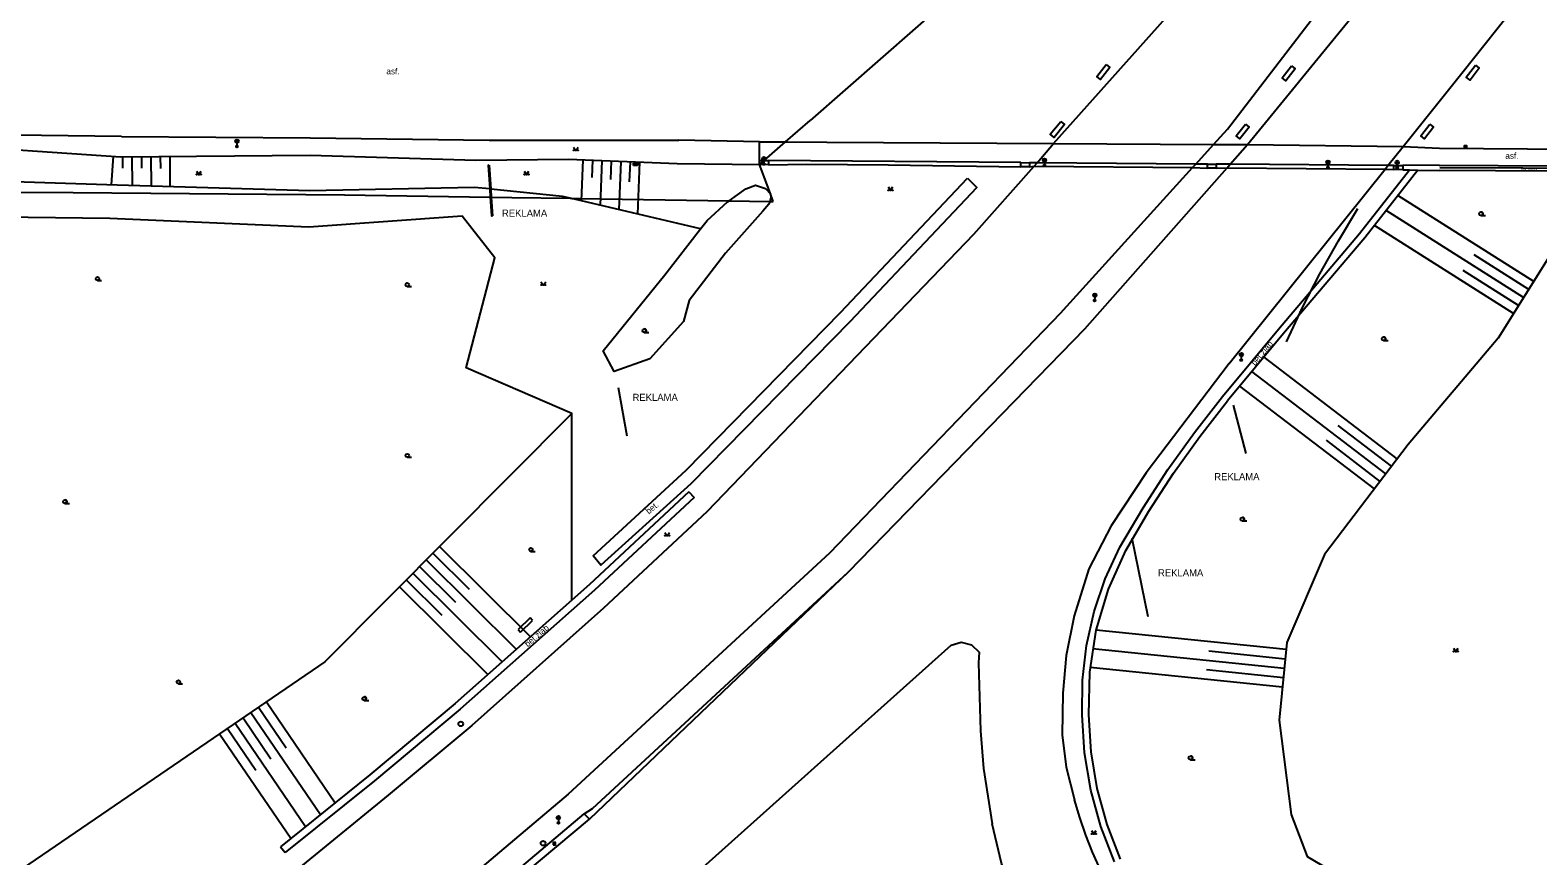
# Model space of a CAD drawing. Extents: x -602419 to -601554, y -1162937 to -1162362.
# Drawn here: x -601894 to -601734.4, y -1162806.1 to -1162718.7 of the extents above; entities that cross this region are included whole.
import ezdxf

# ---------------------------------------------------------------- set-up
doc = ezdxf.new("R2010")
doc.units = 0
doc.layers.add('Podklad', color=7, linetype='Continuous')

msp = doc.modelspace()

# ---------------------------------------------------------------- linework, layer by layer
at = {"layer": 'Podklad'}
for p, q in [((-601872.2825, -1162730.6), (-601872.0175, -1162730.335)), ((-601872.2825, -1162730.335), (-601872.0175, -1162730.6)), ((-601872.15, -1162730.655), (-601872.15, -1162731.03)), ((-601742.225, -1162731.1), (-601741.975, -1162731.1)), ((-601816.5025, -1162732.46), (-601816.2375, -1162732.195)), ((-601816.5025, -1162732.195), (-601816.2375, -1162732.46)), ((-601816.37, -1162732.515), (-601816.37, -1162732.89)), ((-601786.8025, -1162732.61), (-601786.5375, -1162732.345)), ((-601786.8025, -1162732.345), (-601786.5375, -1162732.61)), ((-601786.67, -1162732.665), (-601786.67, -1162733.04)), ((-601756.7925, -1162732.83), (-601756.5275, -1162732.565)), ((-601756.7925, -1162732.565), (-601756.5275, -1162732.83)), ((-601756.66, -1162732.885), (-601756.66, -1162733.26)), ((-601749.4625, -1162732.85), (-601749.1975, -1162732.585)), ((-601749.4625, -1162732.585), (-601749.1975, -1162732.85)), ((-601749.33, -1162732.905), (-601749.33, -1162733.28)), ((-601740.47, -1162738.3375), (-601739.97, -1162738.3375)), ((-601886.92, -1162745.2075), (-601886.4825, -1162745.2075)), ((-601854.12, -1162745.8475), (-601853.6825, -1162745.8475)), ((-601781.4774, -1162746.8856), (-601781.2033, -1162746.63)), ((-601781.4682, -1162746.6208), (-601781.2126, -1162746.8949)), ((-601781.3469, -1162746.9452), (-601781.36, -1162747.32)), ((-601829.05, -1162750.7075), (-601828.55, -1162750.7075)), ((-601750.78, -1162751.5575), (-601750.28, -1162751.5575)), ((-601765.9674, -1162753.1856), (-601765.6933, -1162752.93)), ((-601765.9582, -1162752.9208), (-601765.7026, -1162753.1949)), ((-601765.8369, -1162753.2452), (-601765.85, -1162753.62)), ((-601854.12, -1162763.9075), (-601853.6825, -1162763.9075)), ((-601890.38, -1162768.7875), (-601889.88, -1162768.7875)), ((-601765.74, -1162770.6375), (-601765.24, -1162770.6375)), ((-601841.03, -1162773.8675), (-601840.5925, -1162773.8675)), ((-601878.35, -1162787.8675), (-601877.9125, -1162787.8675)), ((-601858.7, -1162789.6175), (-601858.2, -1162789.6175)), ((-601771.22, -1162795.8875), (-601770.72, -1162795.8875)), ((-601838.2625, -1162802.15), (-601837.9975, -1162801.885)), ((-601838.2625, -1162801.885), (-601837.9975, -1162802.15)), ((-601838.13, -1162802.205), (-601838.13, -1162802.58)), ((-601838.685, -1162804.77), (-601838.435, -1162804.77))]:
    msp.add_line(p, q, dxfattribs=at)
for points in [[(-601793.98, -1162712.96), (-601794.4894, -1162713.4059), (-601796.6372, -1162715.2857), (-601811.4818, -1162728.2775)], [(-601785.71, -1162730.7199), (-601773.83, -1162717.43), (-601771.84, -1162715.44)], [(-601768.78, -1162730.81), (-601767.31, -1162729.19), (-601756.8, -1162715.56)], [(-601765.17, -1162730.83), (-601754.24, -1162717.46), (-601752.54, -1162715.58)], [(-601742.35, -1162723.1), (-601736.4699, -1162715.71)], [(-601780.14, -1162722.37), (-601779.75, -1162722.68), (-601780.75, -1162723.94), (-601781.14, -1162723.63), (-601780.14, -1162722.37)], [(-601760.51, -1162722.51), (-601760.12, -1162722.82), (-601761.12, -1162724.09), (-601761.51, -1162723.77), (-601760.51, -1162722.51)], [(-601741.04, -1162722.45), (-601740.64, -1162722.76), (-601741.62, -1162724.02), (-601742.02, -1162723.7199), (-601741.04, -1162722.45)], [(-601748.71, -1162731.03), (-601742.35, -1162723.1)], [(-601816.82, -1162732.95), (-601816.3348, -1162732.5252), (-601814.0843, -1162730.5554), (-601811.4817, -1162728.2776)], [(-601784.95, -1162728.39), (-601784.56, -1162728.7), (-601785.65, -1162730.07), (-601786.05, -1162729.75), (-601784.95, -1162728.39)], [(-601765.4, -1162728.67), (-601765, -1162728.98), (-601765.99, -1162730.2199), (-601766.38, -1162729.9099), (-601765.4, -1162728.67)], [(-601745.88, -1162728.68), (-601745.48, -1162728.98), (-601746.43, -1162730.21), (-601746.83, -1162729.9), (-601745.88, -1162728.68)], [(-601884.36, -1162729.99), (-601904.12, -1162729.75), (-601924.49, -1162729.7), (-601937.13, -1162729.6599)], [(-601884.36, -1162729.99), (-601864.41, -1162730.11), (-601845.45, -1162730.36)], [(-601845.45, -1162730.36), (-601825.39, -1162730.38)], [(-601816.83, -1162730.54), (-601825.39, -1162730.38)], [(-601816.83, -1162730.54), (-601814.0843, -1162730.5554), (-601809.7199, -1162730.58)], [(-601816.82, -1162732.52), (-601816.83, -1162730.54)], [(-601947.91, -1162731.01), (-601924.66, -1162730.88), (-601904.2, -1162730.78), (-601884.43, -1162732.12), (-601864.39, -1162731.97), (-601846.88, -1162732.47), (-601837.05, -1162732.39)], [(-601885.27, -1162732.06), (-601885.47, -1162735.1)], [(-601884.27, -1162732.12), (-601884.26, -1162733.33)], [(-601883.27, -1162732.11), (-601883.25, -1162735.17)], [(-601882.27, -1162732.1), (-601882.26, -1162733.34)], [(-601881.27, -1162732.1), (-601881.25, -1162735.23)], [(-601880.27, -1162732.09), (-601880.26, -1162733.36)], [(-601879.27, -1162732.08), (-601879.25, -1162735.29)], [(-601836.53, -1162731.095), (-601836.28, -1162731.47), (-601836.03, -1162731.095)], [(-601809.7199, -1162730.58), (-601785.71, -1162730.7199)], [(-601787.76, -1162733.12), (-601787.4491, -1162732.7561), (-601785.71, -1162730.7199)], [(-601785.71, -1162730.7199), (-601768.78, -1162730.81)], [(-601770.99, -1162733.25), (-601770.6641, -1162732.8901), (-601768.78, -1162730.81)], [(-601768.78, -1162730.81), (-601765.17, -1162730.83)], [(-601767.34, -1162733.28), (-601767.013, -1162732.9109), (-601765.17, -1162730.83)], [(-601765.17, -1162730.83), (-601748.71, -1162731.03)], [(-601750.62, -1162733.42), (-601750.32, -1162733.0447), (-601748.71, -1162731.03)], [(-601748.71, -1162731.03), (-601744.87, -1162731.2), (-601726.21, -1162731.37)], [(-601876.45, -1162733.645), (-601876.2, -1162734.02), (-601875.95, -1162733.645)], [(-601845.46, -1162733.01), (-601845.57, -1162733.03), (-601845.4, -1162735.53)], [(-601845.46, -1162733.01), (-601845.29, -1162735.54)], [(-601841.74, -1162733.645), (-601841.49, -1162734.02), (-601841.24, -1162733.645)], [(-601837.05, -1162732.39), (-601825.54, -1162732.85)], [(-601835.53, -1162732.45), (-601835.7, -1162736.8)], [(-601834.53, -1162732.49), (-601834.6, -1162734.31)], [(-601833.53, -1162732.53), (-601833.72, -1162737.26)], [(-601832.53, -1162732.57), (-601832.61, -1162734.54)], [(-601831.53, -1162732.61), (-601831.74, -1162737.73)], [(-601830.53, -1162732.65), (-601830.62, -1162734.77)], [(-601830.18, -1162733.03), (-601830.17, -1162732.81)], [(-601829.76, -1162733.03), (-601830.18, -1162733.03)], [(-601830.17, -1162732.81), (-601829.75, -1162732.81)], [(-601829.75, -1162732.81), (-601829.76, -1162733.03)], [(-601829.53, -1162732.69), (-601829.75, -1162738.19)], [(-601825.54, -1162732.85), (-601816.82, -1162732.95)], [(-601816.82, -1162732.95), (-601816.82, -1162732.52)], [(-601816.82, -1162732.52), (-601816.3348, -1162732.5252), (-601815.89, -1162732.53), (-601815.89, -1162732.71), (-601815.89, -1162732.96)], [(-601815.38, -1162736.85), (-601815.6727, -1162736.0572), (-601815.7178, -1162735.9351), (-601816.82, -1162732.95)], [(-601815.89, -1162732.96), (-601816.82, -1162732.95)], [(-601789.17, -1162732.74), (-601815.89, -1162732.53)], [(-601815.89, -1162732.96), (-601811.83, -1162732.92)], [(-601811.83, -1162732.92), (-601803.2199, -1162732.99), (-601789.17, -1162733.17)], [(-601794.14, -1162740.3), (-601787.76, -1162733.12)], [(-601789.17, -1162732.92), (-601789.17, -1162732.74), (-601788.24, -1162732.75), (-601788.24, -1162732.93), (-601788.24, -1162733.18)], [(-601789.17, -1162733.17), (-601789.17, -1162732.92)], [(-601788.24, -1162733.18), (-601789.17, -1162733.17)], [(-601769.42, -1162732.9), (-601770.6641, -1162732.8901), (-601787.4491, -1162732.7561), (-601788.24, -1162732.75)], [(-601788.24, -1162733.18), (-601787.76, -1162733.12)], [(-601787.76, -1162733.12), (-601770.99, -1162733.25)], [(-601784.98, -1162748.68), (-601770.99, -1162733.25)], [(-601782.4, -1162750.32), (-601767.34, -1162733.28)], [(-601770.99, -1162733.25), (-601769.42, -1162733.33)], [(-601769.42, -1162733.08), (-601769.42, -1162732.9), (-601768.5, -1162732.9), (-601768.5, -1162733.08), (-601768.5, -1162733.33)], [(-601769.42, -1162733.33), (-601769.42, -1162733.08)], [(-601768.5, -1162733.33), (-601769.42, -1162733.33)], [(-601749.68, -1162733.05), (-601750.32, -1162733.0447), (-601767.013, -1162732.9109), (-601768.5, -1162732.9)], [(-601768.5, -1162733.33), (-601767.34, -1162733.28)], [(-601767.82, -1162757.49), (-601761.89, -1162750.36), (-601753.31, -1162740.25), (-601748.03, -1162733.51)], [(-601767.34, -1162733.28), (-601750.62, -1162733.42)], [(-601747.14, -1162733.53), (-601752.77, -1162740.69), (-601761.35, -1162750.82), (-601767.28, -1162757.93)], [(-601767.11, -1162754), (-601750.62, -1162733.42)], [(-601726.17, -1162733.7), (-601732.68, -1162738.79), (-601733.02, -1162742.36), (-601738.66, -1162751.3), (-601748.18, -1162762.56), (-601757.04, -1162774.19), (-601761, -1162783.51), (-601761.84, -1162791.71), (-601760.56, -1162801.67), (-601758.87, -1162806.14), (-601753, -1162809.59)], [(-601750.62, -1162733.42), (-601749.68, -1162733.48)], [(-601749.68, -1162733.23), (-601749.68, -1162733.05), (-601748.74, -1162733.06), (-601748.74, -1162733.24), (-601748.74, -1162733.49)], [(-601749.68, -1162733.48), (-601749.68, -1162733.23)], [(-601748.74, -1162733.49), (-601749.68, -1162733.48)], [(-601744.89, -1162733), (-601748.74, -1162733.06)], [(-601748.74, -1162733.49), (-601748.03, -1162733.51), (-601747.14, -1162733.53), (-601744.86, -1162733.58)], [(-601744.89, -1162733), (-601726.19, -1162733.13)], [(-601726.19, -1162733.13), (-601726.17, -1162733.7), (-601726.26, -1162733.7), (-601727.04, -1162733.69), (-601744.86, -1162733.58)], [(-601727.23, -1162733.38), (-601744.83, -1162733.28)], [(-601845.4, -1162735.53), (-601847.05, -1162735.36), (-601864.45, -1162735.74), (-601884.84, -1162735.12), (-601903.48, -1162734.51), (-601924.34, -1162734.49), (-601947.95, -1162734.55)], [(-601794.83, -1162734.39), (-601793.82, -1162735.38), (-601807.27, -1162749.57), (-601820.33, -1162762.86), (-601824.12, -1162766.71), (-601833.64, -1162775.33), (-601834.46, -1162774.33), (-601824.6, -1162765.26), (-601821.24, -1162761.86), (-601808.28, -1162748.59), (-601794.83, -1162734.39)], [(-601826.86, -1162744.62), (-601823.08, -1162739.76), (-601822.38, -1162738.86), (-601820.21, -1162736.89), (-601820.05, -1162736.78), (-601818.29, -1162735.53), (-601817.25, -1162735.13), (-601816.2, -1162735.49), (-601815.67, -1162736.06), (-601815.64, -1162736.45), (-601815.76, -1162736.84), (-601815.84, -1162737.13), (-601816.49, -1162737.86), (-601820.45, -1162742.31), (-601824.3, -1162747.32), (-601824.87, -1162749.54)], [(-601803.23, -1162735.315), (-601802.98, -1162735.69), (-601802.73, -1162735.315)], [(-601978.25, -1162735.53), (-601954.18, -1162735.627), (-601889.49, -1162735.89), (-601860.77, -1162736.15), (-601845.34, -1162736.39)], [(-601845.29, -1162735.54), (-601845.4, -1162735.53)], [(-601845.4, -1162735.53), (-601845.34, -1162736.39)], [(-601845.34, -1162736.39), (-601845.24, -1162736.39)], [(-601845.34, -1162736.39), (-601845.2, -1162738.38), (-601845.11, -1162738.37)], [(-601845.29, -1162735.54), (-601845.24, -1162736.39)], [(-601823.08, -1162739.76), (-601836.8835, -1162736.5171), (-601837.68, -1162736.33), (-601845.29, -1162735.54)], [(-601845.24, -1162736.39), (-601843.06, -1162736.42), (-601836.8835, -1162736.5171), (-601836.7, -1162736.52), (-601835.88, -1162736.53), (-601820.0506, -1162736.7771), (-601815.7559, -1162736.8441), (-601815.38, -1162736.85)], [(-601845.24, -1162736.39), (-601845.11, -1162738.37)], [(-601734.88, -1162745.31), (-601749.27, -1162736.23)], [(-601836.71, -1162779), (-601836.71, -1162759.26), (-601847.88, -1162754.46), (-601844.85, -1162742.8), (-601848.33, -1162738.42), (-601864.53, -1162739.57), (-601885.6, -1162738.66), (-601902.92, -1162738.45), (-601924.69, -1162739.17), (-601946.88, -1162737.91), (-601963.34, -1162737.04), (-601979.03, -1162737.55), (-601989.84, -1162739.24)], [(-601761.06, -1162751.69), (-601759.35, -1162748.07), (-601757.51, -1162744.51), (-601755.56, -1162741.02), (-601753.49, -1162737.59)], [(-601735.95, -1162747), (-601750.51, -1162737.81)], [(-601737.01, -1162748.69), (-601751.75, -1162739.39)], [(-601794.14, -1162740.3), (-601822.43, -1162769.67)], [(-601735.41, -1162746.15), (-601741.2, -1162742.5)], [(-601824.87, -1162749.54), (-601828.46, -1162753.49), (-601832.23, -1162754.82), (-601833.4, -1162752.64), (-601826.86, -1162744.62)], [(-601736.48, -1162747.84), (-601742.34, -1162744.15)], [(-601839.97, -1162745.335), (-601839.72, -1162745.71), (-601839.47, -1162745.335)], [(-601784.98, -1162748.68), (-601809.42, -1162774.04), (-601837.09, -1162799.55), (-601848.91, -1162809.52), (-601861.6, -1162819.71), (-601867.21, -1162824.05), (-601886.81, -1162838.4), (-601901.63, -1162848.6), (-601920.894, -1162861.0918), (-601922.609, -1162862.2039), (-601926.89, -1162864.98), (-601937.36, -1162871.29)], [(-601782.4, -1162750.32), (-601807.45, -1162776.07), (-601834.85, -1162802.17)], [(-601767.11, -1162754), (-601775.91, -1162765.56), (-601779.61, -1162771.16), (-601781.99, -1162775.7), (-601783.53, -1162780.67), (-601784.37, -1162784.86), (-601784.72, -1162788.85), (-601784.79, -1162793.26), (-601784.37, -1162796.68), (-601783.49, -1162800.14)], [(-601749.32, -1162764.06), (-601763.43, -1162753.31)], [(-601750.53, -1162765.65), (-601764.71, -1162754.85)], [(-601830.84, -1162761.69), (-601831.76, -1162756.57)], [(-601778.68, -1162773.41), (-601776.23, -1162769.26), (-601773.6, -1162765.21), (-601770.79, -1162761.29), (-601767.82, -1162757.49)], [(-601751.75, -1162767.24), (-601765.99, -1162756.39)], [(-601836.71, -1162759.26), (-601862.84, -1162785.54), (-601906.04, -1162815.02)], [(-601778.06, -1162773.75), (-601775.63, -1162769.62), (-601773.02, -1162765.6), (-601770.23, -1162761.71), (-601767.28, -1162757.93)], [(-601766.68, -1162758.39), (-601765.34, -1162763.51)], [(-601749.93, -1162764.85), (-601755.59, -1162760.54)], [(-601751.14, -1162766.45), (-601756.83, -1162762.11)], [(-601824.31, -1162767.57), (-601834.85, -1162777.35), (-601836.71, -1162779), (-601849.04, -1162789.93), (-601858.08, -1162797.5), (-601867.55, -1162805.09)], [(-601823.77, -1162768.15), (-601834.31, -1162777.95), (-601848.52, -1162790.53), (-601857.58, -1162798.12), (-601867.05, -1162805.71)], [(-601824.31, -1162767.57), (-601823.77, -1162768.15)], [(-601822.43, -1162769.67), (-601833.34, -1162779.85), (-601847.28, -1162792.26), (-601856.16, -1162799.64), (-601865.61, -1162807.35)], [(-601826.87, -1162771.845), (-601826.62, -1162772.22), (-601826.37, -1162771.845)], [(-601850.7, -1162773.33), (-601841.09, -1162782.88)], [(-601782.68, -1162791.15), (-601782.65, -1162787.47), (-601782.22, -1162783.82), (-601781.41, -1162780.23), (-601780.23, -1162776.75), (-601778.68, -1162773.41)], [(-601777.42, -1162772.46), (-601775.74, -1162780.75)], [(-601852.11, -1162774.75), (-601842.59, -1162784.21)], [(-601851.41, -1162774.04), (-601847.58, -1162777.84)], [(-601781.98, -1162791.13), (-601781.88, -1162786.63), (-601781.19, -1162782.18), (-601779.91, -1162777.86), (-601778.06, -1162773.75)], [(-601853.52, -1162776.17), (-601844.09, -1162785.54)], [(-601852.82, -1162775.46), (-601849.03, -1162779.23)], [(-601835.39, -1162801.6), (-601834.51, -1162801.05), (-601807.45, -1162776.07)], [(-601854.93, -1162777.59), (-601845.59, -1162786.87)], [(-601854.23, -1162776.88), (-601850.47, -1162780.61)], [(-601841.13, -1162780.88), (-601842.4, -1162782.12)], [(-601842.12, -1162782.41), (-601840.85, -1162781.17)], [(-601840.85, -1162781.17), (-601841.13, -1162780.88)], [(-601842.4, -1162782.12), (-601842.12, -1162782.41)], [(-601761.08, -1162784.24), (-601781.19, -1162782.18)], [(-601826.5, -1162810.58), (-601796.55, -1162783.76)], [(-601796.55, -1162783.76), (-601795.48, -1162783.45), (-601794.39, -1162783.73), (-601793.6, -1162784.52), (-601793.67, -1162785.64)], [(-601761.28, -1162786.23), (-601781.57, -1162784.15)], [(-601761.18, -1162785.24), (-601769.26, -1162784.41)], [(-601743.38, -1162784.095), (-601743.13, -1162784.47), (-601742.88, -1162784.095)], [(-601793.67, -1162785.64), (-601793.46, -1162792.84), (-601793.11, -1162796.82), (-601792.2, -1162802.67)], [(-601761.48, -1162788.22), (-601781.84, -1162786.14)], [(-601761.38, -1162787.23), (-601769.52, -1162786.39)], [(-601870.69, -1162790.9), (-601863.32, -1162801.7)], [(-601869.86, -1162790.33), (-601866.93, -1162794.63)], [(-601869.04, -1162789.77), (-601861.75, -1162800.44)], [(-601779.25, -1162806.7), (-601780.7, -1162802.96), (-601781.77, -1162799.1), (-601782.43, -1162795.15), (-601782.68, -1162791.15)], [(-601778.61, -1162806.4), (-601780.04, -1162802.73), (-601781.09, -1162798.94), (-601781.73, -1162795.06), (-601781.98, -1162791.13)], [(-601873.17, -1162792.59), (-601870.17, -1162796.98)], [(-601872.34, -1162792.02), (-601864.88, -1162802.95)], [(-601871.51, -1162791.46), (-601868.55, -1162795.8)], [(-601873.99, -1162793.15), (-601866.45, -1162804.2)], [(-601780.77, -1162807.45), (-601781.58, -1162805.67), (-601782.3, -1162803.86), (-601782.94, -1162802.01), (-601783.49, -1162800.14)], [(-601859.94, -1162821.88), (-601847.21, -1162811.6), (-601835.39, -1162801.6)], [(-601859.51, -1162822.54), (-601856.32, -1162819.91), (-601846.71, -1162812.11), (-601834.85, -1162802.17)], [(-601835.39, -1162801.6), (-601834.85, -1162802.17)], [(-601785.69, -1162818.33), (-601787.95, -1162814.7), (-601789.8, -1162810.85), (-601791.22, -1162806.83), (-601792.2, -1162802.67)], [(-601781.69, -1162803.385), (-601781.44, -1162803.76), (-601781.19, -1162803.385)], [(-601867.55, -1162805.09), (-601867.05, -1162805.71)]]:
    msp.add_lwpolyline(points, dxfattribs=at)
for points in [[(-601742.225, -1162731.225), (-601741.975, -1162731.225), (-601741.975, -1162730.975), (-601742.225, -1162730.975)], [(-601838.685, -1162804.895), (-601838.435, -1162804.895), (-601838.435, -1162804.645), (-601838.685, -1162804.645)]]:
    msp.add_lwpolyline(points, close=True, dxfattribs=at)
for centre, radius in [((-601872.15, -1162730.4675), 0.1875), ((-601872.15, -1162731.03), 0.1), ((-601872.15, -1162731.03), 0.0723), ((-601872.15, -1162731.03), 0.0438), ((-601836.5051, -1162731.4449), 0.025), ((-601836.0554, -1162731.4449), 0.025), ((-601816.37, -1162732.3275), 0.1875), ((-601816.37, -1162732.89), 0.1), ((-601816.37, -1162732.89), 0.0723), ((-601816.37, -1162732.89), 0.0438), ((-601786.67, -1162732.4775), 0.1875), ((-601786.67, -1162733.04), 0.1), ((-601786.67, -1162733.04), 0.0723), ((-601786.67, -1162733.04), 0.0438), ((-601756.66, -1162732.6975), 0.1875), ((-601756.66, -1162733.26), 0.1), ((-601756.66, -1162733.26), 0.0723), ((-601756.66, -1162733.26), 0.0438), ((-601749.33, -1162732.7175), 0.1875), ((-601749.33, -1162733.28), 0.1), ((-601749.33, -1162733.28), 0.0723), ((-601749.33, -1162733.28), 0.0438), ((-601876.4251, -1162733.9949), 0.025), ((-601875.9754, -1162733.9949), 0.025), ((-601841.7151, -1162733.9949), 0.025), ((-601841.2654, -1162733.9949), 0.025), ((-601803.2051, -1162735.6649), 0.025), ((-601802.7554, -1162735.6649), 0.025), ((-601740.47, -1162738.1498), 0.1875), ((-601886.9201, -1162745.0199), 0.1875), ((-601854.1201, -1162745.66), 0.1875), ((-601839.9451, -1162745.6849), 0.025), ((-601839.4954, -1162745.6849), 0.025), ((-601781.3404, -1162746.7578), 0.1875), ((-601781.36, -1162747.32), 0.1), ((-601781.36, -1162747.32), 0.0723), ((-601781.36, -1162747.32), 0.0438), ((-601829.05, -1162750.5198), 0.1875), ((-601750.78, -1162751.3698), 0.1875), ((-601765.8304, -1162753.0578), 0.1875), ((-601765.85, -1162753.62), 0.1), ((-601765.85, -1162753.62), 0.0723), ((-601765.85, -1162753.62), 0.0438), ((-601854.1201, -1162763.7199), 0.1875), ((-601890.38, -1162768.5998), 0.1875), ((-601765.74, -1162770.4498), 0.1875), ((-601841.0301, -1162773.6799), 0.1875), ((-601826.8451, -1162772.1949), 0.025), ((-601826.3954, -1162772.1949), 0.025), ((-601743.3551, -1162784.4449), 0.025), ((-601742.9054, -1162784.4449), 0.025), ((-601878.3501, -1162787.6799), 0.1875), ((-601858.7, -1162789.4298), 0.1875), ((-601848.46, -1162792.1), 0.25), ((-601771.22, -1162795.6998), 0.1875), ((-601838.13, -1162802.0175), 0.1875), ((-601838.13, -1162802.58), 0.1), ((-601838.13, -1162802.58), 0.0723), ((-601838.13, -1162802.58), 0.0438), ((-601781.6651, -1162803.7349), 0.025), ((-601781.2154, -1162803.7349), 0.025), ((-601839.75, -1162804.72), 0.25)]:
    msp.add_circle(centre, radius, dxfattribs=at)
for centre in [(-601740.4075, -1162738.1498), (-601828.9875, -1162750.5198), (-601750.7175, -1162751.3698), (-601890.3175, -1162768.5998), (-601765.6775, -1162770.4498), (-601858.6375, -1162789.4298), (-601771.1575, -1162795.6998)]:
    msp.add_arc(centre, 0.1875, 260.405931, 99.594069, dxfattribs=at)

# ---------------------------------------------------------------- texts
for s, rotation, p in [('asf.', 359.309808, (-601856.34, -1162723.4)), ('bet.žlab', 49.795008, (-601764.39, -1162754.26)), ('bet.', 39.510547, (-601828.56, -1162769.96)), ('bet.žlab', 40.640672, (-601841.37, -1162784.02))]:
    msp.add_text(s, height=0.65, rotation=rotation, dxfattribs=at).set_placement(p)
for s, height, p in [('asf.', 0.65, (-601737.89, -1162732.34)), ('bet.římsa.', 0.3, (-601736.21, -1162733.6)), ('REKLAMA', 0.75, (-601844.1, -1162738.46)), ('REKLAMA', 0.75, (-601830.28, -1162757.94)), ('REKLAMA', 0.75, (-601768.7, -1162766.33)), ('REKLAMA', 0.75, (-601774.65, -1162776.5))]:
    msp.add_text(s, height=height, dxfattribs=at).set_placement(p)

doc.saveas('drawing.dxf')
